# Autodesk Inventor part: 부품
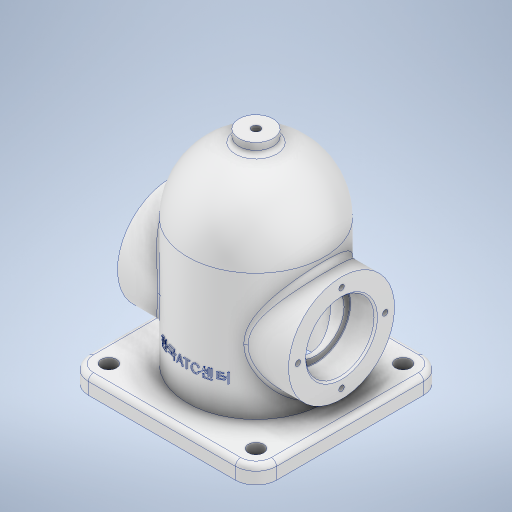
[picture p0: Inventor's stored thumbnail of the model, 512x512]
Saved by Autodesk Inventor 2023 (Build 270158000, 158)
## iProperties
Created: 2025-04
Part Number: 부품
Material: 알루미늄 6061
Document SubType Name: Modeling
Designer: ADMIN_PC
Density: 2.7 g/cm^3
Appearance: 알루미늄 - 평지
Mass: 864.653 g
Surface Area: 803.935 cm^2
Volume: 320.242 cm^3
Author: ADMIN_PC
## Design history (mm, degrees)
sketch "스케치1"
  geometry: L1 (-57.966, 0)-(9.806, 0) reference; L2 (-40, -34.5)-(0, -34.5); L3 (-40, 39.5)-(-40, -34.5); L4 (0, -58.957)-(0, 112.241) reference; L5 (0, 79.5)-(0, -34.5); A1 r 39.378 centre (0, 39.5) between (-0.124, 0.122) and (0.124, 0.122); A2 r 40 centre (0, 39.5) between (0, 79.5) and (-40, 39.5); 1 further point
  constraints: 6 end point, 4 point on circle, 2 centre point, 2 point on line, 1 collinear, 1 horizontal, 1 perpendicular
  dimensions: "d1" = 40 radius of A2; "d3" = 114 distance of L2.end L5.start
revolve "회전1" sketch "스케치1" stored, may be unused: angle "d4" = 90 deg
sketch "스케치2"
  geometry: L1 (-55, -55)-(55, -55); L2 (55, -55)-(55, 55); L3 (55, 55)-(-55, 55); L4 (-55, 55)-(-55, -55); L5 (-55, -55)-(55, 55); L6 (55, -55)-(-55, 55); 1 further point
  constraints: 12 end point, 2 midpoint, 2 parallel, 1 horizontal, 1 perpendicular
  dimensions: "d5" = 110 distance of L3.end L2.end; "d6" = 110 distance of L1.end L2.end
extrude "돌출1" join sketch "스케치2" distance "d7" = 10; taper "d8" = 0 deg
node "작업 평면1"
sketch "스케치4"
  geometry: L1 (-44.5, -55)-(-44.5, 55) reference; L2 (-60.3, 0)-(50.3, 0) reference; C1 r 31 at (3.5, 0); 1 further point
  constraints: 1 centre point, 1 point on line
  dimensions: "d10" = 62 diameter of C1; "d11" = 48 distance from line of L1 C1.centre
extrude "돌출2" join sketch "스케치4" stored distance "d12" = 10; taper "d13" = 0 deg
fillet "모깎기1" dims "d14" = 12
sketch "스케치5"
  geometry: C1 r 4.5 at (-43, -43); C2 r 4.5 at (-43, 43); C3 r 4.5 at (43, 43); C4 r 4.5 at (43, -43); A1 r 12 centre (-43, -43) between (-55, -43) and (-43, -55) reference; A2 r 12 centre (-43, 43) between (-43, 55) and (-55, 43) reference; A3 r 12 centre (43, 43) between (55, 43) and (43, 55) reference; A4 r 12 centre (43, -43) between (43, -55) and (55, -43) reference; 1 further point
  constraints: 4 centre point, 4 coincident
  dimensions: "d15" = 9 diameter of C1; "d16" = 9 diameter of C2; "d17" = 9 diameter of C3; "d18" = 9 diameter of C4
extrude "돌출3" cut sketch "스케치5" extent not by distance; stored distance "d19" = 0; taper "d20" = 0 deg
sketch "스케치6" dims "d21" = 51
  geometry: C1 r 31 at (0, 0) reference; 3 further points
  constraints: 1 coincident, 1 vertical alignment, 2 other
hole "구멍1" sketch "스케치6" at (0, 25.5) diameter "d22" = 3.242; stored, may be unused: countersink angle "d26" = 90 deg, drill point angle "d28" = 118 deg; dims "d23" = 8, "d24" = 4, "d25" = 2, "d27" = 10
sketch "스케치7"
  geometry: C1 r 31 at (0, 0) reference; C2 r 20 at (0, 0); 1 further point
  constraints: 1 centre point, 1 coincident
  dimensions: "d32" = 40 diameter of C2
extrude "돌출4" cut sketch "스케치7" distance "d33" = 15; taper "d34" = 0 deg
sketch "스케치8"
  geometry: C1 r 20 at (0, 0) reference; C2 r 16.5 at (0, 0); 1 further point
  constraints: 1 centre point, 1 coincident
  dimensions: "d35" = 33 diameter of C2
extrude "돌출5" cut sketch "스케치8" extent not by distance; stored distance "d36" = 0; taper "d37" = 0 deg
node "작업 평면2"
sketch "스케치11"
  geometry: C1 r 10 at (0, 0); 1 further point
  constraints: 1 centre point, 1 coincident
  dimensions: "d39" = 20 diameter of C1
extrude "돌출6" join sketch "스케치11" stored distance "d40" = 10; taper "d41" = 0 deg
sketch "스케치13"
  geometry: L1 (-40, -34.5)-(-40, 39.5) reference; L2 (40, -34.5)-(40, 39.5) reference; L3 (-32, 39.5)-(-32, -44.5); L4 (-43, -44.5)-(43, -44.5) reference; L5 (0, 71.5)-(0, -44.5); L6 (-32, -44.5)-(0, -44.5); L7 (0, -69.3)-(0, 104.3) reference; A1 r 40 centre (0, 39.5) between (40, 39.5) and (-40, 39.5) reference; A2 r 32 centre (0, 39.5) between (0, 71.5) and (-32, 39.5); 1 further point
  constraints: 6 end point, 2 point on circle, 2 point on line, 1 centre point, 1 collinear, 1 midpoint, 1 vertical
  dimensions: "d42" = 8 radial gap between concentric circles of A1 A2; "d44" = 32 distance between parallel lines of L5 L3
revolve "회전2" sketch "스케치13" stored, may be unused: angle "d45" = 90 deg
sketch "스케치15"
  geometry: C1 r 32 at (0, 0) reference; 2 further points
  constraints: 1 coincident
hole "구멍2" sketch "스케치15" at (0, 0) diameter "d46" = 4.917; stored, may be unused: countersink angle "d50" = 90 deg, drill point angle "d52" = 118 deg; dims "d47" = 29, "d48" = 4, "d49" = 2, "d51" = 30
chamfer "모따기1" distance "d53" = 1; stored, may be unused: second distance "d54" = 2, angle "d55" = 45 deg
fillet "모깎기2" dims "d56" = 0.3
fillet "모깎기3" dims "d57" = 3
node "작업 평면3"
sketch "스케치16"
  geometry: L1 (43, -44.5)-(-43, -44.5) reference; L2 (0, -69.6)-(0, 106.1) reference; 2 further points
  constraints: 1 point on line, 1 other
  dimensions: "d59" = 30 distance from line of L1 point (0, -14.5)
feature "엠보싱1" sketch "스케치16" dims "d60" = 0.5, "d61" = 0
sketch "스케치17"
  geometry: 1 further point
node "솔리드1"
mirror "미러1"
pattern_circular "원형 패턴1" dims angle "d30" = 360 deg
mirror "미러2"
mirror "미러3"
feature "A9D066F2-1C7D-4E18-AEED-F7BC21143FA4" dims "d46" = 4.917, "d47" = 29, "d48" = 4, "d49" = 2, "d50" = 90 deg, "d51" = 30, "d52" = 118 deg
other parameters: "d38" = 84.5, "d58" = 74
